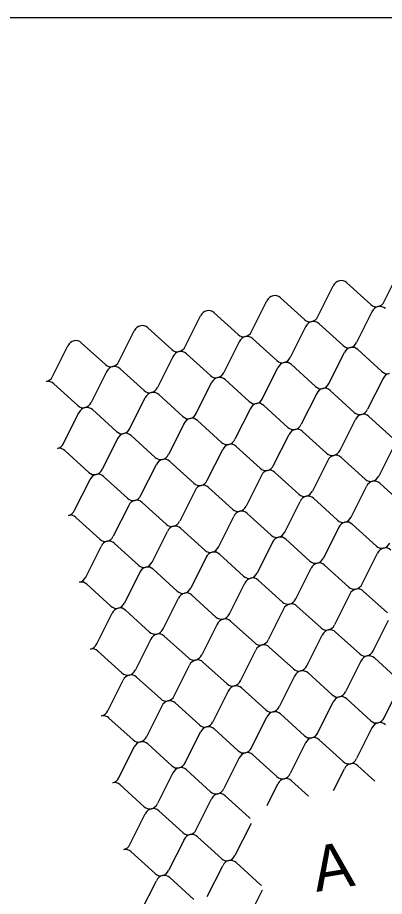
# Model space of a CAD drawing. Extents: x 638850 to 644908, y 297188 to 298900.
# Drawn here: x 640383.5 to 640420.1, y 297950.9 to 298038.5 of the extents above; entities that cross this region are included whole.
import ezdxf

# ---------------------------------------------------------------- set-up
doc = ezdxf.new("R2010")
doc.units = 0
doc.layers.add('1', color=7, linetype='Continuous')
doc.layers.add('5', color=7, linetype='Continuous')

msp = doc.modelspace()

# ---------------------------------------------------------------- linework, layer by layer
at = {"layer": '1'}
msp.add_line((639730.439, 298038.53), (640516.439, 298038.53), dxfattribs=at)
at = {"layer": '5'}
for p, q in [((640420.06, 298010.232), (640421.595, 298013.296)), ((640413.446, 298008.736), (640414.981, 298011.8)), ((640416.32, 298012.103), (640418.721, 298009.929)), ((640406.833, 298007.24), (640408.367, 298010.304)), ((640409.706, 298010.607), (640412.107, 298008.433)), ((640403.092, 298009.111), (640405.493, 298006.937)), ((640418.839, 298009.216), (640417.304, 298006.152)), ((640400.219, 298005.744), (640401.753, 298008.809)), ((640393.605, 298004.249), (640395.139, 298007.313)), ((640396.479, 298007.616), (640398.88, 298005.442)), ((640412.225, 298007.72), (640410.691, 298004.656)), ((640415.965, 298005.849), (640413.564, 298008.023)), ((640409.351, 298004.353), (640406.95, 298006.528)), ((640386.991, 298002.753), (640388.526, 298005.817)), ((640389.865, 298006.12), (640392.266, 298003.946)), ((640405.611, 298006.225), (640404.077, 298003.161)), ((640398.997, 298004.729), (640397.463, 298001.665)), ((640402.738, 298002.858), (640400.337, 298005.032)), ((640414.549, 298002.072), (640416.083, 298005.137)), ((640417.422, 298005.439), (640419.823, 298003.265)), ((640410.808, 298003.944), (640413.21, 298001.77)), ((640392.384, 298003.233), (640390.849, 298000.169)), ((640396.124, 298001.362), (640393.723, 298003.536)), ((640407.935, 298000.577), (640409.469, 298003.641)), ((640401.321, 297999.081), (640402.856, 298002.145)), ((640404.195, 298002.448), (640406.596, 298000.274)), ((640419.941, 298002.553), (640418.407, 297999.489)), ((640389.51, 297999.866), (640387.109, 298002.04)), ((640417.068, 297999.186), (640414.667, 298001.36)), ((640394.707, 297997.585), (640396.242, 298000.649)), ((640397.581, 298000.952), (640399.982, 297998.778)), ((640413.327, 298001.057), (640411.793, 297997.993)), ((640390.967, 297999.456), (640393.368, 297997.282)), ((640406.714, 297999.561), (640405.179, 297996.497)), ((640410.454, 297997.69), (640408.053, 297999.864)), ((640388.093, 297996.089), (640389.628, 297999.154)), ((640418.525, 297998.776), (640420.926, 297996.602)), ((640400.1, 297998.065), (640398.565, 297995.001)), ((640403.84, 297996.194), (640401.439, 297998.368)), ((640415.651, 297995.409), (640417.185, 297998.473)), ((640397.226, 297994.698), (640394.825, 297996.873)), ((640409.037, 297993.913), (640410.572, 297996.977)), ((640411.911, 297997.28), (640414.312, 297995.106)), ((640393.486, 297996.57), (640391.951, 297993.506)), ((640390.612, 297993.203), (640388.211, 297995.377)), ((640402.423, 297992.417), (640403.958, 297995.482)), ((640405.297, 297995.784), (640407.698, 297993.61)), ((640421.044, 297995.889), (640419.509, 297992.825)), ((640398.683, 297994.289), (640401.084, 297992.115)), ((640414.43, 297994.393), (640412.895, 297991.329)), ((640418.17, 297992.522), (640415.769, 297994.696)), ((640395.81, 297990.922), (640397.344, 297993.986)), ((640389.196, 297989.426), (640390.73, 297992.49)), ((640392.069, 297992.793), (640394.47, 297990.619)), ((640407.816, 297992.898), (640406.281, 297989.834)), ((640411.556, 297991.027), (640409.155, 297993.201)), ((640404.942, 297989.531), (640402.541, 297991.705)), ((640416.753, 297988.745), (640418.288, 297991.81)), ((640419.627, 297992.112), (640422.028, 297989.938)), ((640401.202, 297991.402), (640399.668, 297988.338)), ((640394.588, 297989.906), (640393.054, 297986.842)), ((640398.328, 297988.035), (640395.927, 297990.209)), ((640410.139, 297987.25), (640411.674, 297990.314)), ((640413.013, 297990.617), (640415.414, 297988.443)), ((640406.399, 297989.121), (640408.8, 297986.947)), ((640391.715, 297986.539), (640389.314, 297988.713)), ((640403.526, 297985.754), (640405.06, 297988.818)), ((640419.272, 297985.859), (640416.871, 297988.033)), ((640396.912, 297984.258), (640398.446, 297987.322)), ((640399.785, 297987.625), (640402.186, 297985.451)), ((640415.532, 297987.73), (640413.997, 297984.666)), ((640412.658, 297984.363), (640410.257, 297986.537)), ((640390.298, 297982.763), (640391.833, 297985.827)), ((640393.172, 297986.129), (640395.573, 297983.955)), ((640408.918, 297986.234), (640407.384, 297983.17)), ((640402.304, 297984.739), (640400.77, 297981.674)), ((640406.045, 297982.867), (640403.644, 297985.041)), ((640417.856, 297982.082), (640419.39, 297985.146)), ((640411.242, 297980.586), (640412.776, 297983.65)), ((640414.115, 297983.953), (640416.516, 297981.779)), ((640395.691, 297983.243), (640394.156, 297980.179)), ((640399.431, 297981.372), (640397.03, 297983.546)), ((640392.817, 297979.876), (640390.416, 297982.05)), ((640404.628, 297979.091), (640406.162, 297982.155)), ((640407.502, 297982.457), (640409.903, 297980.283)), ((640416.634, 297981.067), (640415.1, 297978.002)), ((640420.374, 297979.195), (640417.973, 297981.369)), ((640398.014, 297977.595), (640399.549, 297980.659)), ((640400.888, 297980.962), (640403.289, 297978.788)), ((640394.274, 297979.466), (640396.675, 297977.292)), ((640410.02, 297979.571), (640408.486, 297976.507)), ((640413.761, 297977.7), (640411.36, 297979.874)), ((640391.4, 297976.099), (640392.935, 297979.163)), ((640418.958, 297975.419), (640420.492, 297978.483)), ((640403.407, 297978.075), (640401.872, 297975.011)), ((640407.147, 297976.204), (640404.746, 297978.378)), ((640400.533, 297974.708), (640398.132, 297976.882)), ((640412.344, 297973.923), (640413.879, 297976.987)), ((640415.218, 297977.29), (640417.619, 297975.116)), ((640396.793, 297976.579), (640395.258, 297973.515)), ((640408.604, 297975.794), (640411.005, 297973.62)), ((640393.919, 297973.212), (640391.518, 297975.386)), ((640405.73, 297972.427), (640407.265, 297975.491)), ((640401.99, 297974.298), (640404.391, 297972.124)), ((640417.737, 297974.403), (640416.202, 297971.339)), ((640421.477, 297972.532), (640419.076, 297974.706)), ((640399.116, 297970.931), (640400.651, 297973.995)), ((640414.863, 297971.036), (640412.462, 297973.21)), ((640392.503, 297969.436), (640394.037, 297972.5)), ((640395.376, 297972.803), (640397.777, 297970.628)), ((640411.123, 297972.907), (640409.588, 297969.843)), ((640404.509, 297971.412), (640402.974, 297968.347)), ((640408.249, 297969.54), (640405.848, 297971.714)), ((640420.06, 297968.755), (640421.595, 297971.819)), ((640416.32, 297970.626), (640418.721, 297968.452)), ((640397.895, 297969.916), (640396.361, 297966.852)), ((640401.635, 297968.045), (640399.234, 297970.219)), ((640413.446, 297967.259), (640414.981, 297970.323)), ((640406.833, 297965.764), (640408.367, 297968.828)), ((640409.706, 297969.131), (640412.107, 297966.956)), ((640395.022, 297966.549), (640392.62, 297968.723)), ((640400.219, 297964.268), (640401.753, 297967.332)), ((640403.092, 297967.635), (640405.493, 297965.461)), ((640418.839, 297967.74), (640417.304, 297964.675)), ((640396.479, 297966.139), (640398.88, 297963.965)), ((640412.225, 297966.244), (640410.691, 297963.18)), ((640415.965, 297964.373), (640413.564, 297966.547)), ((640393.605, 297962.772), (640395.139, 297965.836)), ((640405.611, 297964.748), (640404.077, 297961.684)), ((640409.351, 297962.877), (640406.95, 297965.051)), ((640402.738, 297961.381), (640400.337, 297963.555)), ((640415.003, 297961.503), (640416.083, 297963.66)), ((640417.422, 297963.963), (640419.112, 297962.432)), ((640398.997, 297963.252), (640397.463, 297960.188)), ((640396.124, 297959.885), (640393.723, 297962.059)), ((640408.389, 297960.007), (640409.469, 297962.164)), ((640410.808, 297962.467), (640412.499, 297960.937)), ((640404.195, 297960.971), (640406.596, 297958.797)), ((640401.321, 297957.604), (640402.856, 297960.668)), ((640394.707, 297956.109), (640396.242, 297959.173)), ((640397.581, 297959.476), (640399.982, 297957.301)), ((640406.714, 297958.085), (640405.179, 297955.02)), ((640400.1, 297956.589), (640398.565, 297953.525)), ((640403.84, 297954.718), (640401.439, 297956.892)), ((640397.226, 297953.222), (640394.825, 297955.396)), ((640402.423, 297950.941), (640403.958, 297954.005)), ((640405.297, 297954.308), (640407.698, 297952.134)), ((640395.81, 297949.445), (640397.344, 297952.509)), ((640398.683, 297952.812), (640401.084, 297950.638)), ((640407.816, 297951.421), (640406.281, 297948.357))]:
    msp.add_line(p, q, dxfattribs=at)
for centre, start_param, end_param in [((640415.75, 298011.349), 0.272792, 1.163814), ((640415.75, 298011.349), 5.664956, 6.555978), ((640409.136, 298009.853), 0.272792, 1.163814), ((640409.136, 298009.853), 5.664956, 6.555978), ((640419.291, 298010.683), 2.523363, 3.414385), ((640419.291, 298010.683), 3.414385, 4.305406), ((640402.522, 298008.357), 0.272792, 1.163814), ((640402.522, 298008.357), 5.664956, 6.555978), ((640419.608, 298008.765), 0.272792, 1.163814), ((640419.608, 298008.765), 5.664956, 6.555978), ((640412.677, 298009.187), 2.523363, 3.414385), ((640412.994, 298007.269), 0.272792, 1.163814), ((640412.677, 298009.187), 3.414385, 4.305406), ((640412.994, 298007.269), 5.664956, 6.555978), ((640395.909, 298006.862), 0.272792, 1.163814), ((640395.909, 298006.862), 5.664956, 6.555978), ((640406.063, 298007.691), 2.523363, 3.414385), ((640406.381, 298005.773), 0.272792, 1.163814), ((640406.063, 298007.691), 3.414385, 4.305406), ((640406.381, 298005.773), 5.664956, 6.555978), ((640389.295, 298005.366), 0.272792, 1.163814), ((640389.295, 298005.366), 5.664956, 6.555978), ((640399.449, 298006.196), 3.414385, 4.305406), ((640416.535, 298006.603), 2.523363, 3.414385), ((640416.852, 298004.685), 0.272792, 1.163814), ((640416.535, 298006.603), 3.414385, 4.305406), ((640416.852, 298004.685), 5.664956, 6.555978), ((640399.449, 298006.196), 2.523363, 3.414385), ((640399.767, 298004.278), 0.272792, 1.163814), ((640399.767, 298004.278), 5.664956, 6.555978), ((640392.836, 298004.7), 2.523363, 3.414385), ((640392.836, 298004.7), 3.414385, 4.305406), ((640393.153, 298002.782), 5.664956, 6.555978), ((640409.921, 298005.108), 2.523363, 3.414385), ((640410.239, 298003.19), 0.272792, 1.163814), ((640409.921, 298005.108), 3.414385, 4.305406), ((640410.239, 298003.19), 5.664956, 6.555978), ((640393.153, 298002.782), 0.272792, 1.163814), ((640403.308, 298003.612), 3.414385, 4.305406), ((640420.393, 298004.019), 2.523363, 3.414385), ((640420.71, 298002.102), 0.272792, 1.163814), ((640386.222, 298003.204), 3.414385, 4.305406), ((640386.539, 298001.286), 5.664956, 6.555978), ((640403.308, 298003.612), 2.523363, 3.414385), ((640403.625, 298001.694), 0.272792, 1.163814), ((640403.625, 298001.694), 5.664956, 6.555978), ((640413.779, 298002.524), 3.414385, 4.305406), ((640396.694, 298002.116), 2.523363, 3.414385), ((640396.694, 298002.116), 3.414385, 4.305406), ((640397.011, 298000.198), 5.664956, 6.555978), ((640413.779, 298002.524), 2.523363, 3.414385), ((640414.097, 298000.606), 0.272792, 1.163814), ((640414.097, 298000.606), 5.664956, 6.555978), ((640397.011, 298000.198), 0.272792, 1.163814), ((640407.166, 298001.028), 3.414385, 4.305406), ((640390.08, 298000.62), 2.523363, 3.414385), ((640390.397, 297998.702), 0.272792, 1.163814), ((640390.08, 298000.62), 3.414385, 4.305406), ((640390.397, 297998.702), 5.664956, 6.555978), ((640407.166, 298001.028), 2.523363, 3.414385), ((640407.483, 297999.11), 0.272792, 1.163814), ((640407.483, 297999.11), 5.664956, 6.555978), ((640417.637, 297999.94), 3.414385, 4.305406), ((640400.552, 297999.532), 2.523363, 3.414385), ((640400.869, 297997.614), 0.272792, 1.163814), ((640400.552, 297999.532), 3.414385, 4.305406), ((640400.869, 297997.614), 5.664956, 6.555978), ((640417.637, 297999.94), 2.523363, 3.414385), ((640417.955, 297998.022), 0.272792, 1.163814), ((640417.955, 297998.022), 5.664956, 6.555978), ((640411.024, 297998.444), 2.523363, 3.414385), ((640411.024, 297998.444), 3.414385, 4.305406), ((640393.938, 297998.036), 2.523363, 3.414385), ((640394.255, 297996.119), 0.272792, 1.163814), ((640393.938, 297998.036), 3.414385, 4.305406), ((640394.255, 297996.119), 5.664956, 6.555978), ((640411.341, 297996.526), 0.272792, 1.163814), ((640411.341, 297996.526), 5.664956, 6.555978), ((640387.324, 297996.541), 3.414385, 4.305406), ((640404.41, 297996.948), 2.523363, 3.414385), ((640404.727, 297995.03), 0.272792, 1.163814), ((640404.41, 297996.948), 3.414385, 4.305406), ((640404.727, 297995.03), 5.664956, 6.555978), ((640387.641, 297994.623), 5.664956, 6.555978), ((640414.882, 297995.86), 2.523363, 3.414385), ((640414.882, 297995.86), 3.414385, 4.305406), ((640397.796, 297995.453), 2.523363, 3.414385), ((640398.113, 297993.535), 0.272792, 1.163814), ((640397.796, 297995.453), 3.414385, 4.305406), ((640398.113, 297993.535), 5.664956, 6.555978), ((640415.199, 297993.942), 0.272792, 1.163814), ((640415.199, 297993.942), 5.664956, 6.555978), ((640391.182, 297993.957), 3.414385, 4.305406), ((640408.268, 297994.364), 2.523363, 3.414385), ((640408.585, 297992.447), 0.272792, 1.163814), ((640408.268, 297994.364), 3.414385, 4.305406), ((640408.585, 297992.447), 5.664956, 6.555978), ((640391.182, 297993.957), 2.523363, 3.414385), ((640391.499, 297992.039), 0.272792, 1.163814), ((640391.499, 297992.039), 5.664956, 6.555978), ((640401.654, 297992.869), 3.414385, 4.305406), ((640418.74, 297993.276), 2.523363, 3.414385), ((640418.74, 297993.276), 3.414385, 4.305406), ((640401.654, 297992.869), 2.523363, 3.414385), ((640401.971, 297990.951), 0.272792, 1.163814), ((640401.971, 297990.951), 5.664956, 6.555978), ((640419.057, 297991.358), 0.272792, 1.163814), ((640419.057, 297991.358), 5.664956, 6.555978), ((640395.04, 297991.373), 3.414385, 4.305406), ((640412.126, 297991.781), 2.523363, 3.414385), ((640412.443, 297989.863), 0.272792, 1.163814), ((640412.126, 297991.781), 3.414385, 4.305406), ((640412.443, 297989.863), 5.664956, 6.555978), ((640395.04, 297991.373), 2.523363, 3.414385), ((640395.358, 297989.455), 0.272792, 1.163814), ((640395.358, 297989.455), 5.664956, 6.555978), ((640405.512, 297990.285), 3.414385, 4.305406), ((640388.426, 297989.877), 3.414385, 4.305406), ((640388.744, 297987.959), 5.664956, 6.555978), ((640405.512, 297990.285), 2.523363, 3.414385), ((640405.829, 297988.367), 0.272792, 1.163814), ((640405.829, 297988.367), 5.664956, 6.555978), ((640398.898, 297988.789), 2.523363, 3.414385), ((640398.898, 297988.789), 3.414385, 4.305406), ((640415.984, 297989.197), 2.523363, 3.414385), ((640416.301, 297987.279), 0.272792, 1.163814), ((640415.984, 297989.197), 3.414385, 4.305406), ((640416.301, 297987.279), 5.664956, 6.555978), ((640399.216, 297986.871), 0.272792, 1.163814), ((640399.216, 297986.871), 5.664956, 6.555978), ((640409.37, 297987.701), 3.414385, 4.305406), ((640392.285, 297987.293), 2.523363, 3.414385), ((640392.602, 297985.375), 0.272792, 1.163814), ((640392.285, 297987.293), 3.414385, 4.305406), ((640392.602, 297985.375), 5.664956, 6.555978), ((640409.37, 297987.701), 2.523363, 3.414385), ((640409.687, 297985.783), 0.272792, 1.163814), ((640409.687, 297985.783), 5.664956, 6.555978), ((640402.756, 297986.205), 2.523363, 3.414385), ((640402.756, 297986.205), 3.414385, 4.305406), ((640419.842, 297986.613), 2.523363, 3.414385), ((640420.159, 297984.695), 0.272792, 1.163814), ((640419.842, 297986.613), 3.414385, 4.305406), ((640420.159, 297984.695), 5.664956, 6.555978), ((640403.074, 297984.287), 0.272792, 1.163814), ((640403.074, 297984.287), 5.664956, 6.555978), ((640413.228, 297985.117), 3.414385, 4.305406), ((640396.143, 297984.709), 2.523363, 3.414385), ((640396.46, 297982.792), 0.272792, 1.163814), ((640396.143, 297984.709), 3.414385, 4.305406), ((640396.46, 297982.792), 5.664956, 6.555978), ((640413.228, 297985.117), 2.523363, 3.414385), ((640413.545, 297983.199), 0.272792, 1.163814), ((640413.545, 297983.199), 5.664956, 6.555978), ((640406.614, 297983.621), 2.523363, 3.414385), ((640406.614, 297983.621), 3.414385, 4.305406), ((640389.529, 297983.214), 3.414385, 4.305406), ((640389.846, 297981.296), 5.664956, 6.555978), ((640406.932, 297981.703), 0.272792, 1.163814), ((640406.932, 297981.703), 5.664956, 6.555978), ((640417.086, 297982.533), 3.414385, 4.305406), ((640400.001, 297982.126), 2.523363, 3.414385), ((640400.318, 297980.208), 0.272792, 1.163814), ((640400.001, 297982.126), 3.414385, 4.305406), ((640400.318, 297980.208), 5.664956, 6.555978), ((640417.086, 297982.533), 2.523363, 3.414385), ((640417.404, 297980.615), 0.272792, 1.163814), ((640417.404, 297980.615), 5.664956, 6.555978), ((640393.387, 297980.63), 3.414385, 4.305406), ((640410.472, 297981.037), 2.523363, 3.414385), ((640410.472, 297981.037), 3.414385, 4.305406), ((640393.387, 297980.63), 2.523363, 3.414385), ((640393.704, 297978.712), 0.272792, 1.163814), ((640393.704, 297978.712), 5.664956, 6.555978), ((640410.79, 297979.12), 0.272792, 1.163814), ((640410.79, 297979.12), 5.664956, 6.555978), ((640403.859, 297979.542), 2.523363, 3.414385), ((640404.176, 297977.624), 0.272792, 1.163814), ((640403.859, 297979.542), 3.414385, 4.305406), ((640404.176, 297977.624), 5.664956, 6.555978), ((640397.245, 297978.046), 3.414385, 4.305406), ((640414.331, 297978.454), 2.523363, 3.414385), ((640414.331, 297978.454), 3.414385, 4.305406), ((640414.648, 297976.536), 5.664956, 6.555978), ((640397.245, 297978.046), 2.523363, 3.414385), ((640397.562, 297976.128), 0.272792, 1.163814), ((640397.562, 297976.128), 5.664956, 6.555978), ((640414.648, 297976.536), 0.272792, 1.163814), ((640390.631, 297976.55), 3.414385, 4.305406), ((640407.717, 297976.958), 2.523363, 3.414385), ((640408.034, 297975.04), 0.272792, 1.163814), ((640407.717, 297976.958), 3.414385, 4.305406), ((640408.034, 297975.04), 5.664956, 6.555978), ((640390.948, 297974.632), 5.664956, 6.555978), ((640401.103, 297975.462), 3.414385, 4.305406), ((640418.189, 297975.87), 2.523363, 3.414385), ((640418.506, 297973.952), 0.272792, 1.163814), ((640418.189, 297975.87), 3.414385, 4.305406), ((640418.506, 297973.952), 5.664956, 6.555978), ((640401.103, 297975.462), 2.523363, 3.414385), ((640401.42, 297973.544), 0.272792, 1.163814), ((640401.42, 297973.544), 5.664956, 6.555978), ((640394.489, 297973.966), 2.523363, 3.414385), ((640394.489, 297973.966), 3.414385, 4.305406), ((640411.575, 297974.374), 2.523363, 3.414385), ((640411.892, 297972.456), 0.272792, 1.163814), ((640411.575, 297974.374), 3.414385, 4.305406), ((640411.892, 297972.456), 5.664956, 6.555978), ((640394.806, 297972.048), 0.272792, 1.163814), ((640394.806, 297972.048), 5.664956, 6.555978), ((640404.961, 297972.878), 3.414385, 4.305406), ((640404.961, 297972.878), 2.523363, 3.414385), ((640405.278, 297970.96), 0.272792, 1.163814), ((640405.278, 297970.96), 5.664956, 6.555978), ((640398.347, 297971.382), 2.523363, 3.414385), ((640398.347, 297971.382), 3.414385, 4.305406), ((640415.433, 297971.79), 2.523363, 3.414385), ((640415.75, 297969.872), 0.272792, 1.163814), ((640415.433, 297971.79), 3.414385, 4.305406), ((640415.75, 297969.872), 5.664956, 6.555978), ((640398.664, 297969.465), 0.272792, 1.163814), ((640398.664, 297969.465), 5.664956, 6.555978), ((640408.819, 297970.294), 3.414385, 4.305406), ((640391.733, 297969.887), 3.414385, 4.305406), ((640392.051, 297967.969), 5.664956, 6.555978), ((640408.819, 297970.294), 2.523363, 3.414385), ((640409.136, 297968.376), 0.272792, 1.163814), ((640409.136, 297968.376), 5.664956, 6.555978), ((640402.205, 297968.799), 2.523363, 3.414385), ((640402.205, 297968.799), 3.414385, 4.305406), ((640402.522, 297966.881), 5.664956, 6.555978), ((640419.291, 297969.206), 2.523363, 3.414385), ((640419.608, 297967.288), 0.272792, 1.163814), ((640419.291, 297969.206), 3.414385, 4.305406), ((640419.608, 297967.288), 5.664956, 6.555978), ((640402.522, 297966.881), 0.272792, 1.163814), ((640412.677, 297967.71), 3.414385, 4.305406), ((640395.591, 297967.303), 2.523363, 3.414385), ((640395.909, 297965.385), 0.272792, 1.163814), ((640395.591, 297967.303), 3.414385, 4.305406), ((640395.909, 297965.385), 5.664956, 6.555978), ((640412.677, 297967.71), 2.523363, 3.414385), ((640412.994, 297965.793), 0.272792, 1.163814), ((640412.994, 297965.793), 5.664956, 6.555978), ((640406.063, 297966.215), 2.523363, 3.414385), ((640406.381, 297964.297), 0.272792, 1.163814), ((640406.063, 297966.215), 3.414385, 4.305406), ((640406.381, 297964.297), 5.664956, 6.555978), ((640416.535, 297965.127), 3.414385, 4.305406), ((640399.449, 297964.719), 2.523363, 3.414385), ((640399.767, 297962.801), 0.272792, 1.163814), ((640399.449, 297964.719), 3.414385, 4.305406), ((640399.767, 297962.801), 5.664956, 6.555978), ((640416.535, 297965.127), 2.523363, 3.414385), ((640416.852, 297963.209), 0.272792, 1.163814), ((640416.852, 297963.209), 5.664956, 6.555978), ((640392.836, 297963.223), 3.414385, 4.305406), ((640409.921, 297963.631), 2.523363, 3.414385), ((640410.239, 297961.713), 0.272792, 1.163814), ((640409.921, 297963.631), 3.414385, 4.305406), ((640410.239, 297961.713), 5.664956, 6.555978), ((640393.153, 297961.305), 5.664956, 6.555978), ((640403.308, 297962.135), 2.523363, 3.414385), ((640403.625, 297960.217), 0.272792, 1.163814), ((640403.308, 297962.135), 3.414385, 4.305406), ((640403.625, 297960.217), 5.664956, 6.555978), ((640396.694, 297960.639), 3.414385, 4.305406), ((640396.694, 297960.639), 2.523363, 3.414385), ((640397.011, 297958.722), 0.272792, 1.163814), ((640397.011, 297958.722), 5.664956, 6.555978), ((640407.166, 297959.551), 2.523363, 2.681852), ((640400.552, 297958.056), 3.414385, 4.305406), ((640407.483, 297957.633), 1.005325, 1.163814), ((640400.552, 297958.056), 2.523363, 3.414385), ((640400.869, 297956.138), 0.272792, 1.163814), ((640400.869, 297956.138), 5.664956, 6.555978), ((640393.938, 297956.56), 3.414385, 4.305406), ((640394.255, 297954.642), 5.664956, 6.555978), ((640404.41, 297955.472), 3.414385, 4.305406), ((640404.41, 297955.472), 2.523363, 3.414385), ((640404.727, 297953.554), 0.272792, 1.163814), ((640404.727, 297953.554), 5.664956, 6.555978), ((640397.796, 297953.976), 2.523363, 3.414385), ((640398.113, 297952.058), 0.272792, 1.163814), ((640397.796, 297953.976), 3.414385, 4.305406), ((640398.113, 297952.058), 5.664956, 6.555978), ((640408.268, 297952.888), 2.523363, 2.681852), ((640408.585, 297950.97), 1.005325, 1.163814)]:
    msp.add_ellipse(centre, major_axis=(0.079, 0.976), ratio=0.893529, start_param=start_param, end_param=end_param, dxfattribs=at)

# ---------------------------------------------------------------- texts
at = {"layer": '1'}
msp.add_text('A', height=4.5, rotation=9.46768, dxfattribs=at).set_placement((640413.297, 297951.384))

doc.saveas('drawing.dxf')
